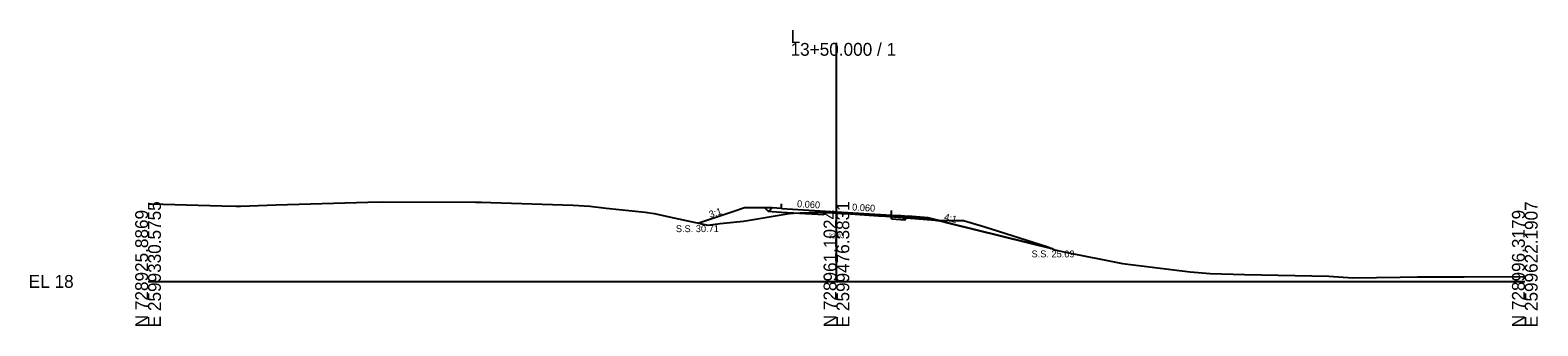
# Model space of a CAD drawing. Extents: x -26 to 3303, y -10 to 9555.
# Drawn here: x -25.7 to 302.8, y 6990.3 to 7054.8 of the extents above; entities that cross this region are included whole.
import ezdxf

# ---------------------------------------------------------------- set-up
doc = ezdxf.new("R2010")
doc.units = 0
for name, color, linetype in [('Exist Cross Section Cell', 7, 'Continuous'), ('Exist XS Center Line Elevation Label', 7, 'Continuous'), ('Exist XS Ground Line', 7, 'Continuous'), ('Prop XS Ditch Slope Text', 7, 'Continuous'), ('Prop XS Dump Level', 7, 'Continuous'), ('Prop XS Earthwork Shape', 7, 'Continuous'), ('Prop XS EOT Tick Mark', 7, 'Continuous'), ('Prop XS Finish Grade', 7, 'Continuous'), ('Prop XS Finish Grade Earthwork', 7, 'Continuous'), ('Prop XS Finish Grade Paved Shoulder', 7, 'Continuous'), ('Prop XS Finish Grade Pavement', 7, 'Continuous'), ('Prop XS Pvmt Edge Slope', 7, 'Continuous'), ('Prop XS SE Text', 7, 'Continuous'), ('Prop XS Side Slope Text', 7, 'Continuous'), ('Prop XS SS Elevation Text', 7, 'Continuous'), ('Prop XS Subgrade Earthwork', 7, 'Continuous')]:
    doc.layers.add(name, color=color, linetype=linetype)

msp = doc.modelspace()

# ---------------------------------------------------------------- linework, layer by layer
at = {"layer": 'Exist Cross Section Cell'}
for p, q in [((150, 7000), (150, 7052.04)), ((0, 7000), (150, 7000)), ((150, 7000), (300, 7000))]:
    msp.add_line(p, q, dxfattribs=at)
at = {"layer": 'Exist XS Ground Line'}
msp.add_lwpolyline([(0, 7016.94), (0.69, 7016.94), (16.09, 7016.5), (19.17, 7016.4), (19.73, 7016.4), (20.12, 7016.41), (27.95, 7016.75), (47.92, 7017.27), (51.02, 7017.35), (71.38, 7017.32), (72.67, 7017.3), (74.72, 7017.21), (92.64, 7016.65), (96.27, 7016.43), (99.79, 7016.02), (108.35, 7015.15), (110.26, 7014.85), (114.57, 7013.87), (121.99, 7012.28), (124.69, 7012.63), (129.73, 7013.16), (137.52, 7014.45), (140.15, 7014.91), (143.97, 7015.03), (147.22, 7015.12), (150, 7014.93), (153.07, 7014.73), (159.17, 7014.31), (160.7, 7014.22), (171.6, 7013.38), (174.55, 7013.31), (177.67, 7013.27), (182.35, 7011.89), (196.03, 7007.54), (197.57, 7006.93), (199.54, 7006.48), (212.34, 7003.94), (218.77, 7003.1), (227.06, 7002.11), (231.44, 7001.76), (238.9, 7001.5), (257.3, 7001.15), (262.5, 7000.79), (272.81, 7000.94), (276.65, 7001), (286.8, 7001.03), (300, 7001.08)], dxfattribs=at)
at = {"layer": 'Prop XS Dump Level'}
for p, q in [((138, 7015.92), (150, 7015.2)), ((150, 7015.2), (162, 7014.48))]:
    msp.add_line(p, q, dxfattribs=at)
at = {"layer": 'Prop XS Earthwork Shape'}
for points in [[(135.21, 7015.25), (134.43, 7016.04), (130, 7016.04), (127.64, 7015.25), (120, 7012.71), (121.99, 7012.28), (124.69, 7012.63), (129.73, 7013.16), (137.52, 7014.45), (140.15, 7014.91), (140.67, 7014.92), (138, 7015.08), (136, 7015.2)], [(138, 7015.08), (136, 7015.2), (135.21, 7015.25), (134.43, 7016.04), (130, 7016.04), (127.64, 7015.25), (120, 7012.71), (121.99, 7012.28), (124.69, 7012.63), (129.73, 7013.16), (137.52, 7014.45), (140.15, 7014.91), (140.67, 7014.92)], [(147.22, 7014.53), (140.67, 7014.92), (143.97, 7015.03), (147.22, 7015.12)], [(147.22, 7014.53), (140.67, 7014.92), (143.97, 7015.03), (147.22, 7015.12)], [(171.6, 7013.38), (172.02, 7013.37), (170, 7013.88), (165.64, 7014.23), (165.28, 7013.87)], [(165.64, 7014.23), (170, 7013.88), (172.02, 7013.37), (171.6, 7013.38), (165.28, 7013.87)], [(162, 7013.64), (164, 7013.52), (164.89, 7013.47), (165.28, 7013.87), (162, 7014.12)], [(162, 7013.64), (164, 7013.52), (164.89, 7013.47), (165.28, 7013.87), (162, 7014.12)], [(172.02, 7013.37), (174.55, 7013.31), (177.67, 7013.27), (182.35, 7011.89), (196.03, 7007.54), (197.17, 7007.09), (174.8, 7012.68)], [(172.02, 7013.37), (174.55, 7013.31), (177.67, 7013.27), (182.35, 7011.89), (196.03, 7007.54), (197.17, 7007.09), (174.8, 7012.68)]]:
    msp.add_lwpolyline(points, close=True, dxfattribs=at)
at = {"layer": 'Prop XS EOT Tick Mark'}
for p, q in [((138, 7015.92), (138, 7016.92)), ((162, 7014.48), (162, 7015.48))]:
    msp.add_line(p, q, dxfattribs=at)
at = {"layer": 'Prop XS Finish Grade'}
for p, q in [((136, 7016.04), (134.43, 7016.04)), ((164, 7014.36), (165.64, 7014.23))]:
    msp.add_line(p, q, dxfattribs=at)
at = {"layer": 'Prop XS Finish Grade Earthwork'}
for p, q in [((127.64, 7015.25), (120, 7012.71)), ((130, 7016.04), (127.64, 7015.25)), ((134.43, 7016.04), (130, 7016.04)), ((165.64, 7014.23), (170, 7013.88)), ((170, 7013.88), (174.8, 7012.68)), ((174.8, 7012.68), (197.17, 7007.09))]:
    msp.add_line(p, q, dxfattribs=at)
at = {"layer": 'Prop XS Finish Grade Paved Shoulder'}
for p, q in [((138, 7015.92), (136, 7016.04)), ((162, 7014.48), (164, 7014.36))]:
    msp.add_line(p, q, dxfattribs=at)
at = {"layer": 'Prop XS Finish Grade Pavement'}
for p, q in [((138, 7015.92), (150, 7015.2)), ((150, 7015.2), (162, 7014.48))]:
    msp.add_line(p, q, dxfattribs=at)
at = {"layer": 'Prop XS Pvmt Edge Slope'}
for p, q in [((135.21, 7015.25), (134.43, 7016.04)), ((136, 7016.04), (135.21, 7015.25)), ((164, 7014.36), (164.89, 7013.47)), ((164.89, 7013.47), (165.64, 7014.23))]:
    msp.add_line(p, q, dxfattribs=at)
at = {"layer": 'Prop XS Subgrade Earthwork'}
for p, q in [((135.21, 7015.25), (134.43, 7016.04)), ((136, 7015.2), (135.21, 7015.25)), ((138, 7015.08), (136, 7015.2)), ((147.22, 7014.53), (138, 7015.08)), ((147.22, 7014.53), (147.22, 7015.12)), ((164.89, 7013.47), (165.64, 7014.23)), ((162, 7013.64), (162, 7014.12)), ((162, 7013.64), (164, 7013.52)), ((164, 7013.52), (164.89, 7013.47))]:
    msp.add_line(p, q, dxfattribs=at)

# ---------------------------------------------------------------- texts
at = {"layer": 'Exist Cross Section Cell'}
for s, p in [('L', (140, 7052.04)), ('13+50.000 / 1', (140, 7049.24)), ('EL 18', (-26, 6998.6))]:
    msp.add_text(s, height=2.8, dxfattribs=at).set_placement(p)
for s, p in [('N 728925.8869', (0, 6990)), ('E 2599330.5755', (2.8, 6990)), ('N 728961.1024', (150, 6990)), ('E 2599476.3831', (152.8, 6990)), ('N 728996.3179', (300, 6990)), ('E 2599622.1907', (302.8, 6990))]:
    msp.add_text(s, height=2.8, rotation=90, dxfattribs=at).set_placement(p)
at = {"layer": 'Exist XS Center Line Elevation Label'}
msp.add_text('32.93', height=1, dxfattribs=at).set_placement((148.27, 7009.43))
at = {"layer": 'Prop XS Ditch Slope Text'}
msp.add_text('4:1', height=1.5, rotation=345.9638, dxfattribs=at).set_placement((173.34, 7013.41))
at = {"layer": 'Prop XS Dump Level'}
for s, height, p in [('Case1', 0.04, (130, 7016)), ('Eop', 0.3, (147.22, 7014.82)), ('Case1', 0.04, (170, 7013.84)), ('Eop', 0.3, (171.6, 7013.08))]:
    msp.add_text(s, height=height, dxfattribs=at).set_placement(p)
at = {"layer": 'Prop XS SE Text'}
for p in [(141.38, 7016.22), (153.38, 7015.5)]:
    msp.add_text('0.060', height=1.5, rotation=356.5664, dxfattribs=at).set_placement(p)
at = {"layer": 'Prop XS Side Slope Text'}
msp.add_text('3:1', height=1.5, rotation=18.4349, dxfattribs=at).set_placement((122.52, 7013.85))
at = {"layer": 'Prop XS SS Elevation Text'}
for s, p in [('S.S. 30.71', (115.01, 7010.76)), ('S.S. 25.09', (192.52, 7005.26))]:
    msp.add_text(s, height=1.5, dxfattribs=at).set_placement(p)

doc.saveas('drawing.dxf')
